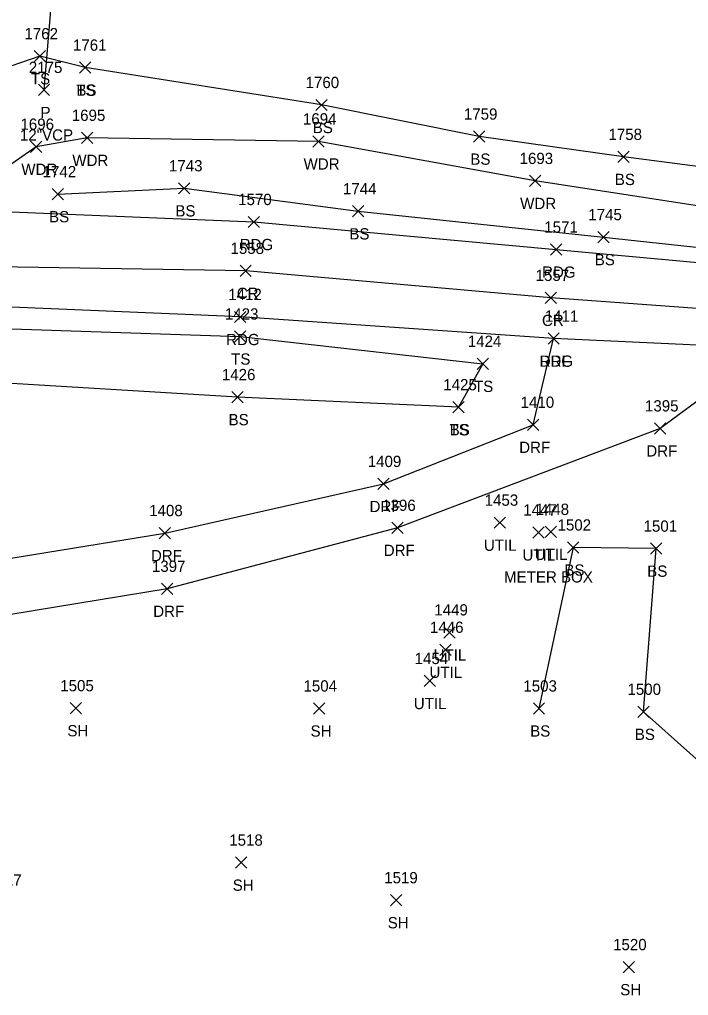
# Model space of a CAD drawing. Extents: x 1609623 to 1616187, y 756677 to 762826.
# Drawn here: x 1610056.5 to 1610175.1, y 761626.7 to 761799.9 of the extents above; entities that cross this region are included whole.
import ezdxf

# ---------------------------------------------------------------- set-up
doc = ezdxf.new("R2010")
doc.units = 0
for name, color, linetype in [('D_A', 7, 'Continuous'), ('D_C', 7, 'Continuous'), ('D_I', 7, 'Continuous'), ('D_TIC', 7, 'Continuous'), ('DCP', 7, 'Continuous'), ('L_A', 7, 'Continuous'), ('L_I', 7, 'Continuous'), ('L_TIC', 7, 'Continuous'), ('LAWA', 7, 'Continuous'), ('LELB', 7, 'Continuous'), ('P_A', 7, 'Continuous'), ('P_I', 7, 'Continuous'), ('P_TIC', 7, 'Continuous'), ('PEU', 7, 'Continuous'), ('PRC', 7, 'Continuous'), ('R_A', 7, 'Continuous'), ('R_I', 7, 'Continuous'), ('R_TIC', 7, 'Continuous'), ('RDF', 7, 'Continuous'), ('U_A', 7, 'Continuous'), ('U_C', 7, 'Continuous'), ('U_I', 7, 'Continuous'), ('UDEFAULT', 7, 'Continuous')]:
    doc.layers.add(name, color=color, linetype=linetype)

msp = doc.modelspace()

# ---------------------------------------------------------------- linework, layer by layer
at = {"layer": 'D_TIC'}
for points in [[(1610059.82, 761786.43), (1610061.82, 761788.43)], [(1610061.82, 761786.43), (1610059.82, 761788.43)]]:
    msp.add_lwpolyline(points, dxfattribs=at)
at = {"layer": 'DCP'}
msp.add_lwpolyline([(1610064.58, 761832.63), (1610060.82, 761787.43)], dxfattribs=at)
at = {"layer": 'L_TIC'}
for points in [[(1610059.09, 761792.42), (1610061.09, 761794.42)], [(1610061.09, 761792.42), (1610059.09, 761794.42)], [(1610067.13, 761790.39), (1610069.13, 761792.39)], [(1610069.13, 761790.39), (1610067.13, 761792.39)], [(1610067.13, 761790.39), (1610069.13, 761792.39)], [(1610069.13, 761790.39), (1610067.13, 761792.39)], [(1610109.05, 761783.76), (1610111.05, 761785.76)], [(1610111.05, 761783.76), (1610109.05, 761785.76)], [(1610067.49, 761777.93), (1610069.49, 761779.93)], [(1610069.49, 761777.93), (1610067.49, 761779.93)], [(1610136.99, 761778.15), (1610138.99, 761780.15)], [(1610138.99, 761778.15), (1610136.99, 761780.15)], [(1610058.44, 761776.35), (1610060.44, 761778.35)], [(1610060.44, 761776.35), (1610058.44, 761778.35)], [(1610108.49, 761777.29), (1610110.49, 761779.29)], [(1610110.49, 761777.29), (1610108.49, 761779.29)], [(1610162.62, 761774.55), (1610164.62, 761776.55)], [(1610164.62, 761774.55), (1610162.62, 761776.55)], [(1610146.91, 761770.28), (1610148.91, 761772.28)], [(1610148.91, 761770.28), (1610146.91, 761772.28)], [(1610062.27, 761767.93), (1610064.27, 761769.93)], [(1610064.27, 761767.93), (1610062.27, 761769.93)], [(1610084.68, 761768.97), (1610086.68, 761770.97)], [(1610086.68, 761768.97), (1610084.68, 761770.97)], [(1610115.54, 761764.89), (1610117.54, 761766.89)], [(1610117.54, 761764.89), (1610115.54, 761766.89)], [(1610159.06, 761760.31), (1610161.06, 761762.31)], [(1610161.06, 761760.31), (1610159.06, 761762.31)], [(1610094.6, 761742.67), (1610096.6, 761744.67)], [(1610096.6, 761742.67), (1610094.6, 761744.67)], [(1610137.67, 761737.82), (1610139.67, 761739.82)], [(1610139.67, 761737.82), (1610137.67, 761739.82)], [(1610094.12, 761731.91), (1610096.12, 761733.91)], [(1610096.12, 761731.91), (1610094.12, 761733.91)], [(1610133.33, 761730.12), (1610135.33, 761732.12)], [(1610135.33, 761730.12), (1610133.33, 761732.12)], [(1610133.33, 761730.12), (1610135.33, 761732.12)], [(1610135.33, 761730.12), (1610133.33, 761732.12)], [(1610153.67, 761705.22), (1610155.67, 761707.22)], [(1610155.67, 761705.22), (1610153.67, 761707.22)], [(1610168.37, 761705.02), (1610170.37, 761707.02)], [(1610170.37, 761705.02), (1610168.37, 761707.02)], [(1610065.48, 761676.7), (1610067.48, 761678.7)], [(1610067.48, 761676.7), (1610065.48, 761678.7)], [(1610108.61, 761676.65), (1610110.61, 761678.65)], [(1610110.61, 761676.65), (1610108.61, 761678.65)], [(1610147.61, 761676.65), (1610149.61, 761678.65)], [(1610149.61, 761676.65), (1610147.61, 761678.65)], [(1610166.15, 761676.06), (1610168.15, 761678.06)], [(1610168.15, 761676.06), (1610166.15, 761678.06)], [(1610094.8, 761649.29), (1610096.8, 761651.29)], [(1610096.8, 761649.29), (1610094.8, 761651.29)], [(1610122.29, 761642.62), (1610124.29, 761644.62)], [(1610124.29, 761642.62), (1610122.29, 761644.62)], [(1610163.53, 761630.74), (1610165.53, 761632.74)], [(1610165.53, 761630.74), (1610163.53, 761632.74)]]:
    msp.add_lwpolyline(points, dxfattribs=at)
at = {"layer": 'LAWA'}
msp.add_lwpolyline([(1610105.26, 761813.02), (1610140.61, 761813.42), (1610167.68, 761812.65), (1610195.19, 761811.82), (1610200.47, 761794.62), (1610201.65, 761767.6), (1610187.83, 761765.14), (1610147.91, 761771.28), (1610109.49, 761778.29), (1610068.49, 761778.93), (1610059.44, 761777.35), (1610050.54, 761771.19), (1610026.67, 761771.55), (1610012.41, 761775.03), (1609988.62, 761770.46), (1609964.66, 761759.68), (1609934.55, 761749.72), (1609900.52, 761743.76), (1609861.36, 761735.79), (1609834.63, 761731.47), (1609803.94, 761726.14)], dxfattribs=at)
at = {"layer": 'LELB'}
for points in [[(1610068.13, 761791.39), (1610060.09, 761793.42), (1610029.16, 761782.79), (1610013.18, 761785.65)], [(1610188.09, 761772.39), (1610163.62, 761775.55), (1610137.99, 761779.15), (1610110.05, 761784.76), (1610068.13, 761791.39)], [(1610063.27, 761768.93), (1610085.68, 761769.97), (1610116.54, 761765.89), (1610160.06, 761761.31), (1610185.8, 761758.52), (1610217.74, 761757.98), (1610252.18, 761759.72), (1610250.87, 761771.88)], [(1609807.34, 761695.39), (1609890.2, 761715.59), (1609943.65, 761729), (1609995.4, 761739.57), (1610047.96, 761745.26), (1610095.6, 761743.67), (1610138.67, 761738.82), (1610134.33, 761731.12)], [(1610134.33, 761731.12), (1610095.12, 761732.91), (1610048.19, 761735.72), (1609997.47, 761731.21), (1609946.49, 761720.77), (1609892.01, 761708.1), (1609809.24, 761687.22)], [(1610331.58, 761719.03), (1610334.04, 761728.28), (1610332.98, 761728.3), (1610331.88, 761725.41), (1610319.31, 761722.82), (1610270.59, 761718.07), (1610241.74, 761657.34), (1610217.07, 761660.78), (1610191.82, 761655.02), (1610167.15, 761677.06), (1610169.37, 761706.02), (1610154.67, 761706.22), (1610148.61, 761677.65)]]:
    msp.add_lwpolyline(points, dxfattribs=at)
at = {"layer": 'P_TIC'}
for points in [[(1610097.04, 761762.99), (1610099.04, 761764.99)], [(1610099.04, 761762.99), (1610097.04, 761764.99)], [(1610150.67, 761758.1), (1610152.67, 761760.1)], [(1610152.67, 761758.1), (1610150.67, 761760.1)], [(1610095.59, 761754.33), (1610097.59, 761756.33)], [(1610097.59, 761754.33), (1610095.59, 761756.33)], [(1610149.7, 761749.53), (1610151.7, 761751.53)], [(1610151.7, 761749.53), (1610149.7, 761751.53)], [(1610094.63, 761746.13), (1610096.63, 761748.13)], [(1610096.63, 761746.13), (1610094.63, 761748.13)], [(1610150.21, 761742.29), (1610152.21, 761744.29)], [(1610152.21, 761742.29), (1610150.21, 761744.29)]]:
    msp.add_lwpolyline(points, dxfattribs=at)
at = {"layer": 'PEU'}
for points in [[(1609803.09, 761712.98), (1609847.46, 761723.55), (1609889.39, 761733.89), (1609939.02, 761747.01), (1609990.56, 761759.58), (1610047.77, 761766.09), (1610098.04, 761763.99), (1610151.67, 761759.1), (1610189.68, 761755.64), (1610237.76, 761754.25), (1610264.31, 761756.11)], [(1610523.28, 761673.99), (1610480.04, 761689.74), (1610439, 761706.13), (1610392.08, 761720.87), (1610334.48, 761734.06), (1610288.63, 761739.63), (1610237.75, 761740.33), (1610189.36, 761741.54), (1610151.21, 761743.29), (1610095.63, 761747.13), (1610049.42, 761749.13), (1609994.68, 761742.82), (1609943, 761732.03), (1609889.61, 761718.43), (1609806.51, 761697.21)]]:
    msp.add_lwpolyline(points, dxfattribs=at)
at = {"layer": 'PRC'}
msp.add_lwpolyline([(1610601.8, 761670.75), (1610582.15, 761672.46), (1610527.05, 761683.5), (1610483.24, 761698.98), (1610440.53, 761715.33), (1610395.01, 761729.94), (1610335.18, 761743.5), (1610288.69, 761747.54), (1610237.99, 761746.29), (1610189.61, 761747.71), (1610150.7, 761750.53), (1610096.59, 761755.33), (1610048.73, 761756.09), (1609993.41, 761750.2), (1609941.26, 761738.94), (1609887.62, 761725.82), (1609805.01, 761705.08)], dxfattribs=at)
at = {"layer": 'R_TIC'}
for points in [[(1610150.21, 761742.29), (1610152.21, 761744.29)], [(1610152.21, 761742.29), (1610150.21, 761744.29)], [(1610146.57, 761727), (1610148.57, 761729)], [(1610148.57, 761727), (1610146.57, 761729)], [(1610169.1, 761726.36), (1610171.1, 761728.36)], [(1610171.1, 761726.36), (1610169.1, 761728.36)], [(1610120.02, 761716.5), (1610122.02, 761718.5)], [(1610122.02, 761716.5), (1610120.02, 761718.5)], [(1610122.54, 761708.71), (1610124.54, 761710.71)], [(1610124.54, 761708.71), (1610122.54, 761710.71)], [(1610081.25, 761707.78), (1610083.25, 761709.78)], [(1610083.25, 761707.78), (1610081.25, 761709.78)], [(1610081.66, 761697.89), (1610083.66, 761699.89)], [(1610083.66, 761697.89), (1610081.66, 761699.89)]]:
    msp.add_lwpolyline(points, dxfattribs=at)
at = {"layer": 'RDF'}
for points in [[(1609814.26, 761657.5), (1609880.33, 761669.23), (1609931.14, 761680.03), (1609985.37, 761691.5), (1610033.07, 761700.76), (1610082.25, 761708.78), (1610121.02, 761717.5), (1610147.57, 761728), (1610151.21, 761743.29)], [(1610189.36, 761741.54), (1610170.1, 761727.36), (1610123.54, 761709.71), (1610082.66, 761698.89), (1610034.71, 761691.02), (1609986.1, 761683.34), (1609933.94, 761672.88), (1609882.6, 761661.03), (1609815.24, 761649.06)]]:
    msp.add_lwpolyline(points, dxfattribs=at)
at = {"layer": 'UDEFAULT'}
for points in [[(1610140.68, 761709.63), (1610142.68, 761711.63)], [(1610142.68, 761709.63), (1610140.68, 761711.63)], [(1610147.52, 761707.89), (1610149.52, 761709.89)], [(1610149.52, 761707.89), (1610147.52, 761709.89)], [(1610149.69, 761708), (1610151.69, 761710)], [(1610151.69, 761708), (1610149.69, 761710)], [(1610131.75, 761690.15), (1610133.75, 761692.15)], [(1610133.75, 761690.15), (1610131.75, 761692.15)], [(1610131.03, 761687.06), (1610133.03, 761689.06)], [(1610133.03, 761687.06), (1610131.03, 761689.06)], [(1610128.25, 761681.53), (1610130.25, 761683.53)], [(1610130.25, 761681.53), (1610128.25, 761683.53)]]:
    msp.add_lwpolyline(points, dxfattribs=at)

# ---------------------------------------------------------------- texts
at = {"layer": 'D_A'}
msp.add_text('P', height=2, dxfattribs=at).set_placement((1610060.2, 761782.43))
at = {"layer": 'D_C'}
msp.add_text('12"VCP', height=2, dxfattribs=at).set_placement((1610056.56, 761778.43))
at = {"layer": 'D_I'}
msp.add_text('2175', height=2, dxfattribs=at).set_placement((1610058.13, 761790.43))
at = {"layer": 'L_A'}
for s, p in [('TS', (1610058.5, 761788.42)), ('TS', (1610066.54, 761786.39)), ('BS', (1610066.57, 761786.39)), ('BS', (1610108.49, 761779.76)), ('WDR', (1610065.85, 761773.93)), ('WDR', (1610106.86, 761773.29)), ('BS', (1610136.43, 761774.15)), ('WDR', (1610056.8, 761772.35)), ('BS', (1610162.06, 761770.55)), ('WDR', (1610145.27, 761766.28)), ('BS', (1610061.72, 761763.93)), ('BS', (1610084.12, 761764.97)), ('BS', (1610114.98, 761760.89)), ('BS', (1610158.5, 761756.31)), ('TS', (1610094.01, 761738.67)), ('TS', (1610137.08, 761733.82)), ('BS', (1610093.56, 761727.91)), ('TS', (1610132.74, 761726.12)), ('BS', (1610132.77, 761726.12)), ('BS', (1610153.11, 761701.22)), ('BS', (1610167.81, 761701.02)), ('SH', (1610064.97, 761672.7)), ('SH', (1610108.1, 761672.65)), ('BS', (1610147.05, 761672.65)), ('BS', (1610165.6, 761672.06)), ('SH', (1610094.29, 761645.29)), ('SH', (1610121.78, 761638.62)), ('SH', (1610163.02, 761626.74))]:
    msp.add_text(s, height=2, dxfattribs=at).set_placement(p)
at = {"layer": 'L_I'}
for s, p in [('1762', (1610057.35, 761796.42)), ('1761', (1610065.96, 761794.39)), ('1761', (1610065.96, 761794.39)), ('1760', (1610107.22, 761787.76)), ('1695', (1610065.75, 761781.93)), ('1694', (1610106.75, 761781.29)), ('1759', (1610135.29, 761782.15)), ('1696', (1610056.65, 761780.35)), ('1758', (1610160.93, 761778.55)), ('1693', (1610145.17, 761774.28)), ('1743', (1610082.99, 761772.97)), ('1742', (1610060.58, 761771.93)), ('1744', (1610113.85, 761768.89)), ('1745', (1610157.36, 761764.31)), ('1423', (1610092.91, 761746.67)), ('1424', (1610135.98, 761741.82)), ('1426', (1610092.37, 761735.91)), ('1425', (1610131.64, 761734.12)), ('1425', (1610131.64, 761734.12)), ('1502', (1610151.9, 761709.22)), ('1501', (1610167.16, 761709.02)), ('1505', (1610063.71, 761680.7)), ('1504', (1610106.84, 761680.65)), ('1503', (1610145.84, 761680.65)), ('1500', (1610164.3, 761680.06)), ('1518', (1610093.68, 761653.29)), ('1517', (1610050.91, 761646.19)), ('1519', (1610121.16, 761646.62)), ('1520', (1610161.75, 761634.74))]:
    msp.add_text(s, height=2, dxfattribs=at).set_placement(p)
at = {"layer": 'P_A'}
for s, p in [('RDG', (1610095.53, 761758.99)), ('RDG', (1610149.16, 761754.1)), ('CR', (1610095.02, 761750.33)), ('CR', (1610149.14, 761745.53)), ('RDG', (1610093.12, 761742.13)), ('RDG', (1610148.7, 761738.29))]:
    msp.add_text(s, height=2, dxfattribs=at).set_placement(p)
at = {"layer": 'P_I'}
for s, p in [('1570', (1610095.26, 761766.99)), ('1571', (1610149.55, 761762.1)), ('1558', (1610093.9, 761758.33)), ('1557', (1610148.01, 761753.53)), ('1412', (1610093.5, 761750.13)), ('1411', (1610149.65, 761746.29))]:
    msp.add_text(s, height=2, dxfattribs=at).set_placement(p)
at = {"layer": 'R_A'}
for p in [(1610148.75, 761738.29), (1610145.1, 761723), (1610167.64, 761722.36), (1610118.56, 761712.5), (1610079.79, 761703.78), (1610121.08, 761704.71), (1610080.19, 761693.89)]:
    msp.add_text('DRF', height=2, dxfattribs=at).set_placement(p)
at = {"layer": 'R_I'}
for s, p in [('1411', (1610149.65, 761746.29)), ('1410', (1610145.36, 761731)), ('1395', (1610167.41, 761730.36)), ('1409', (1610118.24, 761720.5)), ('1396', (1610120.8, 761712.71)), ('1408', (1610079.48, 761711.78)), ('1397', (1610079.96, 761701.89))]:
    msp.add_text(s, height=2, dxfattribs=at).set_placement(p)
at = {"layer": 'U_A'}
for p in [(1610138.84, 761705.63), (1610145.68, 761703.89), (1610147.86, 761704), (1610129.92, 761686.15), (1610129.19, 761683.06), (1610126.41, 761677.53)]:
    msp.add_text('UTIL', height=2, dxfattribs=at).set_placement(p)
at = {"layer": 'U_C'}
msp.add_text('METER BOX', height=2, dxfattribs=at).set_placement((1610142.41, 761700))
at = {"layer": 'U_I'}
for s, p in [('1453', (1610138.98, 761713.63)), ('1447', (1610145.82, 761711.89)), ('1448', (1610148, 761712)), ('1449', (1610130.05, 761694.15)), ('1446', (1610129.28, 761691.06)), ('1454', (1610126.56, 761685.53))]:
    msp.add_text(s, height=2, dxfattribs=at).set_placement(p)

doc.saveas('drawing.dxf')
